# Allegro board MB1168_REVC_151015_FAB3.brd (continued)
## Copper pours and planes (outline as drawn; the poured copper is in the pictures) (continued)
LCDSEG8 on TOP (solid shape): 68.2,101.47 67.28,101.47 66.77,101.98 67.28,102.49 68.2,102.49
LCDSEG12 on TOP (solid shape): 49.4,143.86 48.9,143.35 48.39,143.86 48.39,144.78 49.4,144.78
LCDSEG13 on TOP (solid shape): 45.59,131.7 44.67,131.7 44.16,132.21 44.67,132.72 45.59,132.72
LCDSEG18 on TOP (solid shape): 52.7,103.89 51.78,103.89 51.28,104.39 51.78,104.9 52.7,104.9
LCDSEG19 on TOP (solid shape): 51.02,104.4 51.53,103.89 50.16,103.89 50.16,104.9 51.53,104.9
LCDSEG24 on TOP (solid shape): 45.59,130.18 44.23,130.18 44.74,130.68 44.23,131.19 45.59,131.19
LCDSEG25 on TOP (solid shape): 43.91,129.16 44.42,128.65 43.05,128.65 43.05,129.67 44.41,129.67
NETC4_2 on TOP (solid shape): 58.42,143.86 57.91,143.35 57.4,143.86 57.4,144.78 58.42,144.78
NETC5_2 on TOP (solid shape): 67.43,143.42 66.93,143.92 66.42,143.41 66.42,144.78 67.43,144.78
NETC22_2 on TOP (solid shape): 44.48,133.73 43.97,133.22 43.05,133.22 43.05,134.24 43.97,134.24
NETC26_2 on TOP (solid shape): 43.91,127.76 44.42,127.25 43.05,127.25 43.05,128.27 44.41,128.27
NETC46_2 on TOP (solid shape): 40.01,97.79 39.08,97.79 38.58,98.3 39.08,98.81 40.01,98.81
NETC46_2 on TOP (solid shape): 51.02,102.36 51.53,101.85 50.16,101.85 50.16,102.87 51.53,102.87
NETC58_1 on TOP (solid shape): 63.12,103.03 62.61,103.54 62.1,103.03 62.1,104.39 63.12,104.39
NETC63_1 on TOP (solid shape): 63.12,98.17 62.1,98.17 62.1,99.53 62.61,99.03 63.12,99.54
NETC105_1 on TOP: 22.61,33.15 25.4,33.15 26.29,32.26 26.29,29.84 24,27.56 24,26.16 23.75,25.91 22.61,25.91 22.35,26.16 22.35,32.89
NETC105_2 on TOP: 9.65,31.5 20.95,31.5 21.84,30.61 21.84,25.53 21.59,25.27 10.54,25.27 8.13,22.86 8.13,17.21 9.27,16.07 10.6,16.07 11.43,15.24 11.43,13.21 10.29,12.06 2.92,12.06 1.78,13.21 1.78,23.62
NETCN5_7 on TOP (solid shape): 71.63,127.89 70.71,127.89 70.2,128.39 70.71,128.9 71.63,128.9
NETCN5_8 on TOP (solid shape): 71.63,126.24 70.71,126.24 70.2,126.74 70.71,127.25 71.63,127.25
NETCN5_11 on TOP (solid shape): 71.63,121.16 70.71,121.16 70.2,121.67 70.71,122.17 71.63,122.17
NETCN5_12 on TOP (solid shape): 71.63,123.06 70.71,123.06 70.2,123.57 70.71,124.08 71.63,124.08
NETCN8_2 on TOP (solid shape): 40.01,99.19 39.08,99.19 38.58,99.69 39.08,100.2 40.01,100.2
NETCN18_1 on TOP: 24,22.1 23.62,21.72 14.35,21.72 13.72,21.08 13.72,16.89 13.46,16.64 9.53,16.64 8.95,17.21 8.95,22.42 11.3,24.77 23.37,24.77 24,24.13
NETJP10_3 on TOP: 88.14,56.26 88.14,52.83 84.2,48.9 52.32,48.9 51.05,50.16 51.05,51.82 51.18,51.94 52.07,51.94 52.32,51.69 52.32,50.8 52.83,50.29 82.17,50.29 82.8,50.93 82.8,53.09 82.93,53.21 83.95,53.21 84.71,53.98 84.71,58.55 86.11,59.94 99.57,59.94 101.35,58.17 101.35,51.56 101.98,50.93 104.01,50.93 104.52,50.42 104.52,48.39 104.01,47.88 99.57,47.88 98.42,49.02 98.42,56.64 97.98,57.09 88.96,57.09
NETJP11_4 on TOP (solid shape): 20.45,44.93 19.94,44.42 19.43,44.93 19.43,45.85 20.45,45.85
NETL9_1 on TOP (solid shape): 87.02,29.09 86.52,28.58 85.6,28.58 85.6,29.59 86.52,29.59
NETL9_1 on TOP (solid shape): 87.02,27.18 86.52,26.67 85.6,26.67 85.6,27.69 86.52,27.69
NETLS1_1 on TOP (solid shape): 52.82,165.64 39.14,164.54 39.14,163.71 52.82,162.63 52.82,162.43 39.16,161.32 39.16,160.5 52.82,159.41 52.82,159.19 39.13,158.08 39.13,157.25 52.81,156.18 52.81,155.97 37.89,155.97 37.89,165.82 52.82,165.82
NETLS1_1 on TOP (solid shape): 87.67,155.98 86.4,155.98 86.4,156.41 72.73,157.49 72.73,157.87 86.4,158.96 86.4,159.63 72.73,160.71 72.73,161.09 86.4,162.19 86.4,162.85 72.72,163.93 72.72,164.32 86.4,165.41 86.4,165.86 87.67,165.86
NETLS1_2 on TOP (solid shape): 69.47,165.63 55.82,164.54 55.82,163.69 69.47,162.62 69.47,162.41 55.83,161.3 55.83,160.48 69.47,159.4 69.47,159.18 55.81,158.1 55.81,157.35 69.47,156.17 69.47,155.96 53.07,155.96 53.07,156.41 39.39,157.48 39.39,157.86 53.07,158.96 53.07,159.64 39.41,160.72 39.41,161.09 53.07,162.2 53.07,162.86 39.41,163.94 39.42,164.32 53.07,165.41 53.07,165.83 69.47,165.83
NETLS1_3 on TOP (solid shape): 86.15,165.67 86.11,165.64 72.48,164.55 72.48,163.7 86.14,162.62 86.15,162.61 86.15,162.42 72.48,161.32 72.48,160.48 86.15,159.39 86.15,159.2 86.14,159.19 72.48,158.1 72.48,157.26 86.12,156.18 86.15,156.15 86.15,155.99 69.72,155.99 69.72,156.4 56.06,157.57 56.06,157.86 69.72,158.94 69.72,159.63 56.08,160.71 56.08,161.08 69.72,162.17 69.72,162.85 56.08,163.92 56.08,164.3 69.72,165.4 69.72,165.84 86.15,165.84
NETR5_1 on TOP (solid shape): 21.97,151.39 20.61,151.39 21.11,151.89 20.6,152.4 21.97,152.4
NETR12_1 on TOP (solid shape): 60.83,143.86 60.33,143.35 59.82,143.86 59.82,144.78 60.83,144.78
NETR13_1 on TOP (solid shape): 69.21,143.42 68.71,143.92 68.2,143.41 68.2,144.78 69.21,144.78
NETR18_1 on TOP (solid shape): 50.93,143.86 50.42,143.35 49.91,143.86 49.91,144.78 50.93,144.78
NETR37_2 on TOP (solid shape): 40.73,130.69 41.24,130.18 39.88,130.18 39.88,131.19 41.24,131.19
NETSB33_2 on TOP (solid shape): 52.7,101.85 51.78,101.85 51.28,102.36 51.78,102.87 52.7,102.87
PA1 on TOP (solid shape): 69.21,143.16 69.21,142.24 68.2,142.24 68.2,143.16 68.7,143.67
PA1 on TOP (solid shape): 70.99,143.16 70.99,142.24 69.97,142.24 69.97,143.16 70.48,143.67
PA2 on TOP (solid shape): 65.66,143.16 65.66,142.24 64.64,142.24 64.64,143.16 65.15,143.67
PA2 on TOP (solid shape): 67.43,143.16 67.43,142.24 66.42,142.24 66.42,143.16 66.93,143.67
PB0 on TOP (solid shape): 60.83,142.24 59.82,142.24 59.82,143.6 60.32,143.1 60.83,143.61
PB0 on TOP (solid shape): 60.83,140.12 60.33,140.62 59.82,140.11 59.82,141.48 60.83,141.48
PB1 on TOP (solid shape): 58.42,142.24 57.4,142.24 57.4,143.6 57.91,143.1 58.42,143.61
PB1 on TOP (solid shape): 58.42,140.12 57.91,140.62 57.4,140.11 57.4,141.48 58.42,141.48
PB3 on TOP (solid shape): 58.17,114.17 56.8,114.17 57.31,114.68 56.8,115.19 58.17,115.19
PB12 on TOP (solid shape): 49.4,142.24 48.39,142.24 48.39,143.6 48.89,143.1 49.4,143.61
PB12 on TOP (solid shape): 50.93,142.24 49.91,142.24 49.91,143.6 50.42,143.1 50.93,143.61
PB13 on TOP (solid shape): 43.91,132.21 44.42,131.7 43.05,131.7 43.05,132.72 44.41,132.72
PB13 on TOP (solid shape): 45.59,133.22 44.23,133.22 44.74,133.73 44.23,134.24 45.59,134.24
PC6 on TOP (solid shape): 42.42,130.18 41.5,130.18 40.99,130.68 41.5,131.19 42.42,131.19
PC6 on TOP (solid shape): 44.48,130.68 43.97,130.18 43.05,130.18 43.05,131.19 43.97,131.19
PC7 on TOP (solid shape): 45.59,128.65 44.67,128.65 44.16,129.16 44.67,129.67 45.59,129.67
PC7 on TOP (solid shape): 45.59,127.25 44.67,127.25 44.16,127.76 44.67,128.27 45.59,128.27
PC14 on TOP (solid shape): 69.94,121.67 70.45,121.16 69.09,121.16 69.09,122.17 70.45,122.17
PC15 on TOP (solid shape): 69.94,123.57 70.45,123.06 69.09,123.06 69.09,124.08 70.45,124.08
PD7 on TOP (solid shape): 63.12,102.77 63.12,101.85 62.1,101.85 62.1,102.77 62.61,103.28
PD7 on TOP (solid shape): 63.12,99.79 62.61,99.28 62.1,99.79 62.1,100.71 63.12,100.71
PH0 on TOP (solid shape): 69.95,126.75 70.46,126.24 69.09,126.24 69.09,127.25 70.45,127.25
PH1 on TOP (solid shape): 69.95,128.4 70.46,127.89 69.09,127.89 69.09,128.9 70.45,128.9
SH0_D on TOP: 77.34,55.37 83.82,55.37 84.07,55.12 84.07,53.85 83.82,53.59 82.8,53.59 82.3,53.09 82.3,51.18 82.17,51.05 77.34,51.05 76.96,51.44 76.96,53.59 77.22,53.85 77.22,55.24
SH1_D on TOP: 57.47,50.8 52.9,50.8 52.83,50.86 52.83,55.18 53.02,55.37 59.5,55.37 59.75,55.12 59.75,53.98 59.5,53.72 58.1,53.72 57.85,53.47 57.85,51.18
SH2_D on TOP: 50.23,50.8 45.66,50.8 45.28,51.18 45.28,54.86 45.78,55.37 52.26,55.37 52.51,55.12 52.51,53.98 52.26,53.72 50.86,53.72 50.61,53.47 50.61,51.18
SH3_D on TOP: 65.09,50.8 60.52,50.8 60.13,51.18 60.13,54.86 60.64,55.37 66.93,55.37 67.18,55.12 67.18,53.98 66.93,53.72 65.72,53.72 65.47,53.47 65.47,51.18
TS_SHIELD on TOP: 36.96,167.89 87.63,167.89 89.15,166.37 89.15,155.19 87.12,153.16 75.82,153.16 75.82,153.16 75.62,153.16 75.31,152.85 75.31,152.65 70.1,147.45 39.75,147.45 36.58,150.62 36.58,167.51 ; 1 cut-out
TS_SHIELD on L2_VCC: 39.37,132.46 39.37,147.17 36.2,150.35 36.2,172.21 92.33,172.21 92.33,153.03 75.71,153.03 66.44,143.76 43.84,143.76 40.77,140.69 40.77,132.82 40.41,132.46
U5V on TOP: 33.17,111.86 34.24,111.86 34.42,111.68 34.42,108 34.24,107.82 31.24,107.82 30.86,108.2 30.86,111.25 31.06,111.46 32.77,111.46
U5V on BOTTOM: 13.34,146.81 13.34,143.76 12.95,143.38 11.94,143.38 7.49,147.83 6.22,147.83 5.97,148.08 5.97,151.13 6.48,151.64 8.51,151.64
U5V on L2_VCC: 12.06,145.54 16,145.54 19.94,141.6 19.94,140.21 21.08,139.06 25.27,139.06 25.4,138.94 25.4,116.84 30.48,111.76 34.04,111.76 34.42,111.38 34.42,107.95 34.16,107.7 30.73,107.7 27.3,111.12 20.83,111.12 17.14,114.81 17.14,137.41 11.3,143.26 11.3,144.78
U5V_STLINK on TOP (solid shape): 20.45,43.31 19.43,43.31 19.43,44.67 19.94,44.16 20.45,44.67
U5V_STLINK on TOP: 44.96,44.58 45.09,44.45 45.09,42.42 44.7,42.04 42.29,42.04 42.16,42.16 42.16,43.05 42.04,43.18 40.51,43.18 40.26,43.43 40.26,44.32 40.51,44.58
U5V_STLINK on BOTTOM: 41.38,44.48 41.38,43.33 41.22,43.18 40.51,43.18 40.26,43.43 40.26,44.48 40.41,44.63 41.22,44.63
USB_VBUS3V3 on TOP: 32,119.76 32.26,120.02 32.26,122.17 31.75,122.68 30.35,122.68 29.97,122.3 29.97,121.59 29.87,121.49 27.94,121.49 27.81,121.36 27.81,119.99 28.04,119.76
USB_VBUS3V3 on TOP: 30.23,116.71 34.42,116.71 34.61,116.52 34.61,114.11 34.42,113.92 34.42,113.33 31.57,113.33 31.37,113.54 31.37,114.3 31.11,114.55 30.18,114.55 29.92,114.81 29.92,116.41
USB_VBUS3V3 on BOTTOM: 32.13,114.3 30.43,114.3 29.91,114.82 29.91,116.12 27.99,118.03 27.99,120.4 28.18,120.59 29.65,120.59 29.92,120.32 29.92,119.18 33.07,116.03 33.07,115.24
VUSB_STLINK on TOP: 47.24,42.93 47.37,43.05 49.91,43.05 50.04,42.93 50.04,42.67 50.29,42.42 53.09,42.42 53.47,42.04 53.47,39.75 51.94,38.23 46.48,38.23 46.23,38.48 46.23,40.13 46.35,40.26 51.44,40.26 51.56,40.39 51.56,40.51 51.44,40.64 47.37,40.64 47.24,40.77

Small or netless copper shapes (teardrops, artwork), in the pictures only: 2 on TOP

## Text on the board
BOTTOM: C
Ref Des/Silkscreen Bottom: STLINK | MFX | Rev.C | B | C | MB1168
Ref Des/Silkscreen Top: +5V | USB | E5V | PSU_E5V | USART2 | Detection | U5V | STlk | 5V | D5V | uSD | GND | PE11 | PE13 | PE15 | PA13 | PD0 | PD3 | PD6 | PD7 | PE7 | PE9 | RF_EEPROM | +3V3 | PE8 | PE10 | PE12 | PE14 | PA12 | PA14 | PD1 | PD5 | USART | 1 <--> 0 | 1=Sys mem | 0=Flash | VBUS | STLINK | BL_Boot0 | Pwr_ext | BL_RST | VDD_MCU | USB_VBUS3V3 | IRDA | DET | LCD | VLCD1 | VLCD2 | VREF+ | VDDA | DAC_OUT1 | ADC_IN5 | 1 | DAC_OUT | VLCD | Det | BOOT0 | PA0 | PH1 | PH10 | PC14 | PE5 | PB6 | Trace | PB2 | PC15 | PE6 | PE4 | PB7 | RESET# | VDD | VDD_ADJ | IDD | ST-LINK/V2 | LPUART | JTAG | PA11 | PC13 | PA5 | PH0 | PH9 | PA4 | IrDA | VDD<1.71V | VDD>1.8V | PD2 | PA9 | PC12 | PA8 | PC11 | PA10 | PC10 | PB9 | PC3 | PB11 | PC4 | VDD_USB | PB10 | Ext LC | PC5 | PB5 | COM | PC6 | PB14 | PC7 | PB13 | PB12 | PC8 | PC9 | VLCD3 | PA15 | PD8 | PB8 | XN | PD9 | PB15 | YP | XP | PD10 | PC2 | YN | PD11 | PC1 | PD12 | PC0 | PD13 | PA3 | PD14 | PA2 | PD15 | PB0 | PE0 | PA7 | MFX | PE1 | PA6 | PE2 | PB4 | PE3 | PB3 | PA1 | PB1 | Over Curret | SWD | S | C | Reset | Wkup/Tamper | Joystick | MB1168 Rev.C | STM32L073Z-EVAL
User.7: FIGURE | SIZE | 12.0 | 30.0 | 33.0 | 36.0 | 38.0 | 40.0 | 48.0 | 53.0 | 95.0 | 28.0 | 39.0 | 47.0 | 59.0 | 126.0 | 138.0 | 51.0x24.0 | 126.0x40.0 | 140.0x50.0 | TOLERANCE | +3.0/-3.0 | +2.0/-2.0 | +5.0/-5.0 | DRILL CHART: TOP to BOTTOM | ALL UNITS ARE IN MILS | PLATED | NON-PLATED | ROTATION | - | 0.000 | 90.000 | QTY | 669 | 7 | 2 | 156 | 18 | 120 | 6 | 3 | 1 | 4 | 1007 | TOTAL HOLES:
User.39: U1
